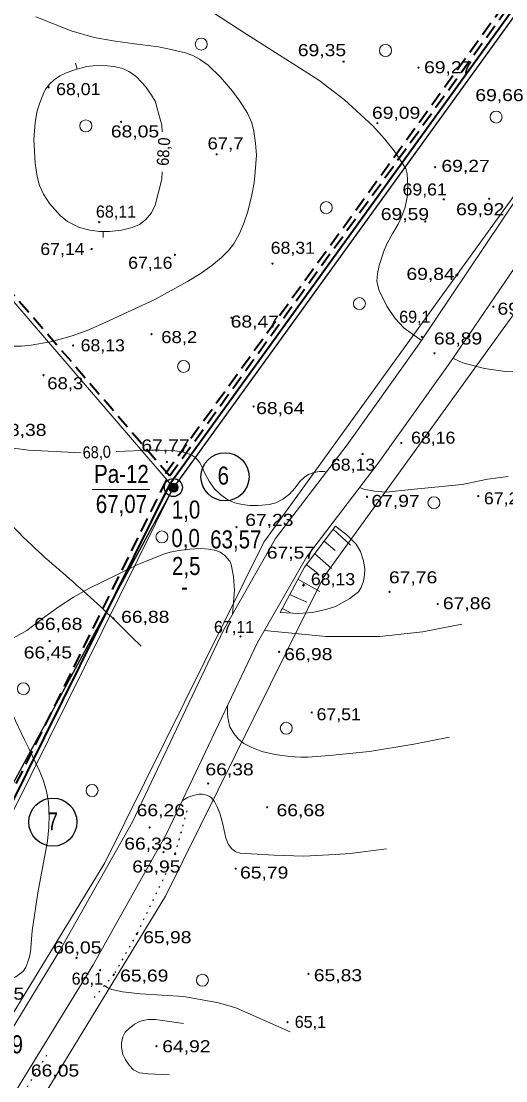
# Model space of a CAD drawing. Extents: x 628176 to 629009, y 6439913 to 6440496.
# Drawn here: x 628522.3 to 628602.9, y 6440112.2 to 6440288.3 of the extents above; entities that cross this region are included whole.
import ezdxf
from ezdxf.enums import TextEntityAlignment as Align

# ---------------------------------------------------------------- set-up
doc = ezdxf.new("R2010")
doc.units = 0
doc.header["$LTSCALE"] = 0.8
doc.linetypes.add('DOTTED', pattern=[1.5, 0.3, -1.2])
doc.linetypes.add('MEDIUM_DASHED', pattern=[4.5, 3, -1.5])
for name, color, linetype, lineweight in [('1', 7, 'Continuous', 13), ('10', 7, 'Continuous', 25), ('11', 7, 'Continuous', 13), ('12', 7, 'Continuous', 13), ('14', 7, 'Continuous', 25), ('16', 7, 'Continuous', 13), ('21', 7, 'MEDIUM_DASHED', 35), ('3', 7, 'Continuous', 13), ('6', 7, 'Continuous', 13)]:
    doc.layers.add(name, color=color, linetype=linetype, lineweight=lineweight)

msp = doc.modelspace()

# ---------------------------------------------------------------- hatches: boundary and pattern name
at = {"layer": '1'}
for points in [[(628576.0425, 6440281.5599, 1), (628575.8425, 6440281.5599, 1)], [(628588.4959, 6440280.5672, 1), (628588.2959, 6440280.5672, 1)], [(628526.9841, 6440277.301, 1), (628526.7841, 6440277.301, 1)], [(628539.0202, 6440271.5559, 1), (628538.8202, 6440271.5559, 1)], [(628581.6671, 6440271.3408, 1), (628581.4671, 6440271.3408, 1)], [(628554.9326, 6440266.1638, 1), (628554.7326, 6440266.1638, 1)], [(628591.2746, 6440264.0147, 1), (628591.0746, 6440264.0147, 1)], [(628592.7042, 6440258.667, 1), (628592.5042, 6440258.667, 1)], [(628600.2509, 6440258.7844, 1), (628600.0509, 6440258.7844, 1)], [(628535.401, 6440254.885, 1), (628535.201, 6440254.885, 1)], [(628589.6342, 6440255.0043, 1), (628589.4342, 6440255.0043, 1)], [(628534.1236, 6440250.4154, 1), (628533.9236, 6440250.4154, 1)], [(628547.9924, 6440249.4589, 1), (628547.7924, 6440249.4589, 1)], [(628564.2251, 6440247.9903, 1), (628564.0251, 6440247.9903, 1)], [(628594.9171, 6440246.1046, 1), (628594.7171, 6440246.1046, 1)], [(628600.9629, 6440240.8324, 1), (628600.7629, 6440240.8324, 1)], [(628557.401, 6440239.0054, 1), (628557.201, 6440239.0054, 1)], [(628544.0917, 6440236.2578, 1), (628543.8917, 6440236.2578, 1)], [(628531.0336, 6440234.3708, 1), (628530.8336, 6440234.3708, 1)], [(628589.0576, 6440235.8239, 1), (628588.8576, 6440235.8239, 1)], [(628591.1757, 6440233.0847, 1), (628590.9757, 6440233.0847, 1)], [(628526.1359, 6440229.434, 1), (628525.9359, 6440229.434, 1)], [(628561.082, 6440224.251, 1), (628560.882, 6440224.251, 1)], [(628585.6579, 6440218.1762, 1), (628585.4579, 6440218.1762, 1)], [(628546.6565, 6440215.0297, 1), (628546.4565, 6440215.0297, 1)], [(628579.2057, 6440216.3368, 1), (628579.0057, 6440216.3368, 1)], [(628579.9466, 6440209.2387, 1), (628579.7466, 6440209.2387, 1)], [(628598.4534, 6440209.3522, 1), (628598.2534, 6440209.3522, 1)], [(628558.2267, 6440204.1828, 1), (628558.0267, 6440204.1828, 1)], [(628567.2897, 6440200.7363, 1), (628567.0897, 6440200.7363, 1)], [(628569.4019, 6440194.5556, 1), (628569.2019, 6440194.5556, 1)], [(628583.6948, 6440193.4364, 1), (628583.4948, 6440193.4364, 1)], [(628591.689, 6440191.4116, 1), (628591.489, 6440191.4116, 1)], [(628537.7623, 6440189.0228, 1), (628537.5623, 6440189.0228, 1)], [(628527.1448, 6440185.2499, 1), (628526.9448, 6440185.2499, 1)], [(628558.8884, 6440186.0188, 1), (628558.6884, 6440186.0188, 1)], [(628565.3116, 6440183.4648, 1), (628565.1116, 6440183.4648, 1)], [(628570.743, 6440173.3816, 1), (628570.543, 6440173.3816, 1)], [(628553.5156, 6440161.5761, 1), (628553.3156, 6440161.5761, 1)], [(628563.3258, 6440157.6225, 1), (628563.1258, 6440157.6225, 1)], [(628543.7771, 6440154.2507, 1), (628543.5771, 6440154.2507, 1)], [(628546.0846, 6440150.1654, 1), (628545.8846, 6440150.1654, 1)], [(628548.0273, 6440149.8668, 1), (628547.8273, 6440149.8668, 1)], [(628558.0998, 6440147.4229, 1), (628557.8998, 6440147.4229, 1)], [(628541.6577, 6440136.6114, 1), (628541.4577, 6440136.6114, 1)], [(628531.6269, 6440132.599, 1), (628531.4269, 6440132.599, 1)], [(628535.5321, 6440130.5527, 1), (628535.3321, 6440130.5527, 1)], [(628537.8175, 6440129.8078, 1), (628537.6175, 6440129.8078, 1)], [(628570.211, 6440129.9301, 1), (628570.011, 6440129.9301, 1)], [(628566.7213, 6440121.9156, 1), (628566.5213, 6440121.9156, 1)], [(628544.8969, 6440117.9094, 1), (628544.6969, 6440117.9094, 1)]]:
    msp.add_hatch(color=256, dxfattribs=at).paths.add_polyline_path(points)
at = {"layer": '10'}
msp.add_hatch(color=256, dxfattribs=at).paths.add_polyline_path([(628548.3757, 6440210.774, 1), (628546.8757, 6440210.774, 1)])

# ---------------------------------------------------------------- linework, layer by layer
at = {"layer": '1'}
for p, q in [((628604.9, 6440259.07), (628588.52, 6440234.65)), ((628611.39, 6440257.62), (628593.63, 6440231.52)), ((628594.82, 6440246.1), (628594.57, 6440246.1)), ((628594.82, 6440246.1), (628594.82, 6440246.35)), ((628594.82, 6440246.1), (628595.07, 6440246.1)), ((628594.82, 6440246.1), (628594.82, 6440245.85)), ((628588.52, 6440234.65), (628576.52, 6440217.86)), ((628593.63, 6440231.52), (628581.69, 6440214.81)), ((628576.52, 6440217.86), (628564.62, 6440202.28)), ((628581.69, 6440214.81), (628569.76, 6440199.19)), ((628577.07, 6440201.21), (628574.21, 6440203.86)), ((628564.62, 6440202.28), (628555.97, 6440187.04)), ((628574.53, 6440200.33), (628572.7, 6440201.87)), ((628569.76, 6440199.19), (628561.61, 6440185)), ((628573.94, 6440197.3), (628571.12, 6440199.79)), ((628571.59, 6440196.52), (628569.72, 6440197.95)), ((628571.98, 6440193.49), (628568.33, 6440195.52)), ((628569.3, 6440194.56), (628569.05, 6440194.56)), ((628569.3, 6440194.56), (628569.3, 6440194.81)), ((628569.3, 6440194.56), (628569.55, 6440194.56)), ((628569.3, 6440194.56), (628569.3, 6440194.31)), ((628569.83, 6440191.73), (628566.97, 6440192.98)), ((628567.04, 6440190), (628565.75, 6440190.69)), ((628555.97, 6440187.04), (628540.83, 6440155.18)), ((628561.61, 6440185), (628546.5, 6440153.23)), ((628540.83, 6440155.18), (628528.77, 6440133.79)), ((628546.5, 6440153.23), (628534.28, 6440131.41)), ((628528.77, 6440133.79), (628516.03, 6440113)), ((628534.28, 6440131.41), (628521.55, 6440110.66))]:
    msp.add_line(p, q, dxfattribs=at)
at = {"layer": '1', "linetype": 'DOTTED', "lineweight": 25}
for p, q in [((628547.93, 6440149.87), (628550.01, 6440157.38)), ((628547.93, 6440149.87), (628541.56, 6440136.61)), ((628541.56, 6440136.61), (628537.72, 6440129.81)), ((628537.72, 6440129.81), (628534.28, 6440125.82)), ((628519.58, 6440105.02), (628527.09, 6440117.27))]:
    msp.add_line(p, q, dxfattribs=at)
at = {"layer": '1'}
msp.add_lwpolyline([(628574.61, 6440204.37), (628569.42, 6440197.55), (628565.37, 6440189.98)], dxfattribs=at)
for centre, radius in [((628552.266, 6440284.4786), 1), ((628582.9206, 6440283.4124), 1), ((628575.9425, 6440281.5599), 0.1), ((628588.3959, 6440280.5672), 0.1), ((628526.8841, 6440277.301), 0.1), ((628601.3148, 6440272.3564), 1), ((628533.0735, 6440270.8839), 1), ((628538.9202, 6440271.5559), 0.1), ((628581.5671, 6440271.3408), 0.1), ((628554.8326, 6440266.1638), 0.1), ((628591.1746, 6440264.0147), 0.1), ((628573.0578, 6440257.2893), 1), ((628592.6042, 6440258.667), 0.1), ((628600.1509, 6440258.7844), 0.1), ((628535.301, 6440254.885), 0.1), ((628589.5342, 6440255.0043), 0.1), ((628534.0236, 6440250.4154), 0.1), ((628547.8924, 6440249.4589), 0.1), ((628564.1251, 6440247.9903), 0.1), ((628594.8171, 6440246.1046), 0.1), ((628578.5646, 6440241.3333), 1), ((628600.8629, 6440240.8324), 0.1), ((628557.301, 6440239.0054), 0.1), ((628543.9917, 6440236.2578), 0.1), ((628530.9336, 6440234.3708), 0.1), ((628588.9576, 6440235.8239), 0.1), ((628591.0757, 6440233.0847), 0.1), ((628549.3338, 6440230.8996), 1), ((628526.0359, 6440229.434), 0.1), ((628560.982, 6440224.251), 0.1), ((628585.5579, 6440218.1762), 0.1), ((628546.5565, 6440215.0297), 0.1), ((628579.1057, 6440216.3368), 0.1), ((628579.8466, 6440209.2387), 0.1), ((628590.9738, 6440208.242), 1), ((628598.3534, 6440209.3522), 0.1), ((628545.7318, 6440202.5545), 1), ((628558.1267, 6440204.1828), 0.1), ((628567.1897, 6440200.7363), 0.1), ((628569.3019, 6440194.5556), 0.1), ((628583.5948, 6440193.4364), 0.1), ((628591.589, 6440191.4116), 0.1), ((628537.6623, 6440189.0228), 0.1), ((628527.0448, 6440185.2499), 0.1), ((628558.7884, 6440186.0188), 0.1), ((628565.2116, 6440183.4648), 0.1), ((628522.6776, 6440177.3207), 1), ((628570.643, 6440173.3816), 0.1), ((628566.4139, 6440170.7558), 1), ((628534.0982, 6440160.4148), 1), ((628553.4156, 6440161.5761), 0.1), ((628563.2258, 6440157.6225), 0.1), ((628543.6771, 6440154.2507), 0.1), ((628545.9846, 6440150.1654), 0.1), ((628547.9273, 6440149.8668), 0.1), ((628557.9998, 6440147.4229), 0.1), ((628541.5577, 6440136.6114), 0.1), ((628531.5269, 6440132.599), 0.1), ((628535.4321, 6440130.5527), 0.1), ((628537.7175, 6440129.8078), 0.1), ((628552.4535, 6440128.8747), 1), ((628570.111, 6440129.9301), 0.1), ((628566.6213, 6440121.9156), 0.1), ((628544.7969, 6440117.9094), 0.1)]:
    msp.add_circle(centre, radius, dxfattribs=at)
at = {"layer": '10'}
for centre, radius in [((628556.2232, 6440212.5587), 4), ((628547.6257, 6440210.774), 0.75), ((628527.5786, 6440155.1573), 4)]:
    msp.add_circle(centre, radius, dxfattribs=at)
at = {"layer": '11'}
for points in [[(628595.11, 6440426.87), (628573.75, 6440350.05), (628485.59, 6440282.78), (628547.63, 6440210.77)], [(628709.76, 6440416.52), (628665.41, 6440371.4), (628640.59, 6440339.47), (628612.95, 6440301.12), (628547.63, 6440210.77)], [(628547.63, 6440210.77), (628520.9, 6440156.84), (628497.5, 6440118.54)]]:
    msp.add_lwpolyline(points, dxfattribs=at)
at = {"layer": '12'}
msp.add_line((628534.13, 6440210.47), (628543.7, 6440210.47), dxfattribs=at)
at = {"layer": '12', "lineweight": 25}
msp.add_circle((628547.6257, 6440210.774), 1.5, dxfattribs=at)
at = {"layer": '14'}
msp.add_lwpolyline([(628648.46, 6440349.59), (628617.39, 6440307.28), (628547.63, 6440210.77), (628497.5, 6440118.54), (628474.19, 6440080.39)], dxfattribs=at)
at = {"layer": '16'}
for points in [[(628523.86, 6440425.63), (628523.12, 6440415.76), (628522.56, 6440410.73), (628519.12, 6440396.74), (628513.8, 6440381.86), (628510.45, 6440374.81), (628499.31, 6440356.42), (628494.72, 6440347.58), (628488, 6440335.91), (628479.91, 6440315.37), (628477.03, 6440304.26), (628475.97, 6440294.36), (628477.03, 6440283.22), (628480.57, 6440271.2), (628486.05, 6440256.7), (628486.58, 6440255.49)], [(628489.38, 6440249.57), (628495.6, 6440238.31), (628503.56, 6440226.46), (628524.07, 6440201.18), (628533.26, 6440193.04), (628542.28, 6440184.38)]]:
    msp.add_spline(points, degree=3, dxfattribs=at)
at = {"layer": '21'}
for points in [[(628595.48, 6440425.23), (628574.45, 6440349.57), (628486.75, 6440282.66), (628547.03, 6440212.69)], [(628704.5, 6440414.58), (628663.6, 6440372.99), (628638.67, 6440340.91), (628611, 6440302.53), (628546.02, 6440212.64)], [(628706.25, 6440415.23), (628664.2, 6440372.46), (628639.31, 6440340.43), (628611.65, 6440302.06), (628547.03, 6440212.69)], [(628546.49, 6440212.09), (628519.5, 6440157.62), (628496.99, 6440120.78)]]:
    msp.add_lwpolyline(points, dxfattribs=at)
at = {"layer": '21', "linetype": 'Continuous', "lineweight": 40}
for points in [[(628708.01, 6440415.87), (628664.8, 6440371.93), (628639.95, 6440339.95), (628612.3, 6440301.59), (628546.94, 6440211.19)], [(628546.94, 6440211.19), (628520.2, 6440157.23), (628496.82, 6440118.96)]]:
    msp.add_lwpolyline(points, dxfattribs=at)
at = {"layer": '3'}
for p, q in [((628524.75, 6440289), (628530.62, 6440286.71)), ((628531.37, 6440281.3), (628531.64, 6440280.33)), ((628545.78, 6440269.88), (628545.69, 6440271)), ((628545.69, 6440262), (628545.77, 6440263.27)), ((628559.29, 6440254.56), (628558.63, 6440253)), ((628585, 6440254.55), (628584.13, 6440253.05)), ((628535.97, 6440252.34), (628535.97, 6440253.34)), ((628584.13, 6440253.05), (628583.23, 6440251.43)), ((628583.32, 6440251.63), (628582.71, 6440250.25)), ((628581.48, 6440244.99), (628581.86, 6440243.53)), ((628581.86, 6440243.53), (628583.13, 6440240.89)), ((628583.13, 6440240.89), (628584.55, 6440238.87)), ((628584.55, 6440238.87), (628586.01, 6440237.27)), ((628586.01, 6440237.27), (628588.89, 6440235.21)), ((628538.09, 6440216.78), (628543.92, 6440217)), ((628543.92, 6440217), (628545.39, 6440217)), ((628583, 6440210), (628587.19, 6440210.42)), ((628544.2, 6440199), (628546, 6440199.68)), ((628554.74, 6440200.28), (628553.48, 6440200.51)), ((628535.63, 6440195), (628541.6, 6440197.9)), ((628541.6, 6440197.9), (628544.2, 6440199)), ((628579.42, 6440196.27), (628579.23, 6440195.18)), ((628579.46, 6440197.18), (628579.42, 6440196.27)), ((628533.55, 6440194), (628535.63, 6440195)), ((628579.23, 6440195.18), (628578.88, 6440194.14)), ((628568.47, 6440189.83), (628565.37, 6440189.98)), ((628557.04, 6440171.01), (628556.74, 6440172.21)), ((628570.02, 6440165.97), (628568.83, 6440165.94)), ((628573.59, 6440166.25), (628570.02, 6440165.97)), ((628526.01, 6440162), (628525.36, 6440163.66)), ((628526.54, 6440160.3), (628526.01, 6440162)), ((628526.54, 6440160.3), (628526.86, 6440158.49)), ((628526.86, 6440158.49), (628526.99, 6440156.33)), ((628526.99, 6440156.33), (628526.9, 6440154.32)), ((628526.9, 6440154.32), (628526.69, 6440151.97)), ((628549.33, 6440121.69), (628544.65, 6440122.35)), ((628539.23, 6440119.46), (628539.61, 6440120.22)), ((628539.61, 6440120.22), (628540.25, 6440120.87)), ((628540.25, 6440120.87), (628541.19, 6440121.59)), ((628539.23, 6440119.46), (628539, 6440118.46)), ((628539, 6440117.69), (628539, 6440118.46)), ((628539, 6440117.69), (628539.23, 6440116.54)), ((628539.61, 6440115.78), (628539.23, 6440116.54)), ((628539.61, 6440115.78), (628540.25, 6440114.75)), ((628543.46, 6440113.29), (628541.99, 6440113.5)), ((628543.46, 6440113.29), (628547.01, 6440113.13))]:
    msp.add_line(p, q, dxfattribs=at)
for points in [[(628552.58, 6440290.77), (628559.18, 6440286.53), (628571.81, 6440278.47), (628576.1, 6440275.19)], [(628530.62, 6440286.71), (628534.44, 6440285.6), (628537.6, 6440285), (628541.55, 6440284.44), (628543.44, 6440284.24), (628545.18, 6440284), (628546.49, 6440283.76), (628549.64, 6440283), (628551, 6440282.53), (628552, 6440282), (628553.39, 6440281), (628555.48, 6440279), (628557.44, 6440276.67), (628558.68, 6440275), (628559.95, 6440273), (628560.68, 6440271.4), (628561.04, 6440270), (628561.31, 6440268), (628561.43, 6440266), (628561.26, 6440263.26), (628561.08, 6440261.44), (628560.7, 6440259.4), (628560, 6440256.67), (628559.29, 6440254.56)], [(628528.79, 6440256), (628527, 6440258), (628526, 6440259.53), (628525.36, 6440261), (628525, 6440262.48), (628524.66, 6440264.66), (628524.44, 6440268.62), (628524.66, 6440271.46), (628525, 6440273.36), (628525.39, 6440274.74), (628526, 6440276.28), (628526.36, 6440277), (628527, 6440277.81), (628527.79, 6440278.52), (628528.72, 6440279.19), (628529.82, 6440279.71), (628531.24, 6440280.22), (628532.39, 6440280.54), (628533.24, 6440280.74), (628533.72, 6440280.81), (628534.28, 6440280.86), (628535.29, 6440280.91), (628536.67, 6440280.86), (628537.75, 6440280.75), (628538.5, 6440280.61), (628539, 6440280.49), (628539.57, 6440280.26), (628540.21, 6440279.94), (628541, 6440279.45), (628541.56, 6440279)], [(628545.69, 6440271), (628544.58, 6440275), (628544, 6440276), (628543, 6440277.45), (628541.56, 6440279)], [(628576.1, 6440275.19), (628580.8, 6440270.89), (628582.75, 6440268.72)], [(628582.75, 6440268.72), (628584.33, 6440266.75), (628586.3, 6440263.8)], [(628586.3, 6440263.8), (628586.54, 6440262.91), (628586.62, 6440260.87), (628586.5, 6440259.06), (628586.16, 6440257.35), (628585.65, 6440255.87), (628585, 6440254.55)], [(628528.79, 6440256), (628530, 6440255), (628532, 6440254), (628533.71, 6440253.55), (628535.32, 6440253.34), (628537, 6440253.34), (628539, 6440253.55), (628540.75, 6440254), (628542, 6440254.51), (628543, 6440255.28), (628544, 6440256.43), (628544.58, 6440257.72), (628545.69, 6440262)], [(628558.63, 6440253), (628557.68, 6440251.29), (628556.82, 6440250.15)], [(628582.71, 6440250.25), (628581.87, 6440247.68), (628581.57, 6440246.37), (628581.48, 6440244.99)], [(628556.82, 6440250.15), (628555.66, 6440249), (628554, 6440247.65), (628552.08, 6440246.3), (628550, 6440245), (628544.53, 6440242), (628537, 6440238.51), (628533.54, 6440237), (628530.82, 6440236), (628529, 6440235.47), (628527.11, 6440235), (628524, 6440234.44), (628522.35, 6440234.29), (628520.65, 6440234.26), (628518.68, 6440234.36)], [(628594.13, 6440232.25), (628595.78, 6440231.52), (628599.36, 6440230.53), (628602.88, 6440230.04), (628605.07, 6440230.1), (628607.25, 6440230.24)], [(628515.25, 6440218.07), (628523.48, 6440217), (628532.28, 6440216.56)], [(628545.39, 6440217), (628547.45, 6440216.92), (628548.69, 6440216.78), (628549.73, 6440216.56), (628550.68, 6440216.16), (628551.37, 6440215.68), (628552.02, 6440214.87), (628552.44, 6440214.17), (628552.94, 6440213.07), (628553.58, 6440211.81), (628554.4, 6440210.62), (628555.54, 6440209.55), (628556.71, 6440208.75), (628557.88, 6440208.25), (628559.05, 6440207.94), (628560.36, 6440207.78), (628561.76, 6440207.78), (628563.57, 6440207.94), (628564.68, 6440208.25), (628565.85, 6440208.83), (628566.95, 6440209.65), (628567.86, 6440210.69), (628568.73, 6440211.81), (628569.48, 6440212.56), (628570.09, 6440212.96), (628571, 6440213.29), (628571.92, 6440213.43), (628572.76, 6440213.43), (628573.07, 6440213.34)], [(628587.19, 6440210.42), (628595.65, 6440211.27), (628599.9, 6440212.15), (628603.33, 6440212.62)], [(628578.61, 6440210.78), (628579.32, 6440210.51), (628581.06, 6440210.15), (628583, 6440210)], [(628579.46, 6440197.18), (628579.27, 6440198.57), (628578.77, 6440200.13), (628578.06, 6440201.33), (628576.61, 6440202.81), (628574.61, 6440204.37)], [(628546, 6440199.68), (628547.1, 6440200), (628548.54, 6440200.32), (628550.38, 6440200.55), (628552.19, 6440200.63), (628553.48, 6440200.51)], [(628554.74, 6440200.28), (628555.43, 6440200), (628556.2, 6440199.5), (628557, 6440198.55), (628557.23, 6440198), (628557.64, 6440196), (628557.77, 6440193.64), (628557.48, 6440189.7)], [(628520.63, 6440185.61), (628521.48, 6440186), (628523.24, 6440187), (628525.88, 6440189), (628528.65, 6440191), (628531, 6440192.55), (628533.55, 6440194)], [(628578.88, 6440194.14), (628578.4, 6440193.44), (628577, 6440192.34), (628574.59, 6440191), (628573, 6440190.47), (628570.75, 6440190), (628568.47, 6440189.83)], [(628562.76, 6440187), (628573, 6440186), (628582, 6440186), (628589.09, 6440186.79), (628595.61, 6440188.07)], [(628522.85, 6440168.85), (628521.36, 6440172), (628518.39, 6440178.54)], [(628556.65, 6440174.57), (628556.65, 6440173.11), (628556.74, 6440172.21)], [(628557.04, 6440171.01), (628557.66, 6440169.87), (628558.44, 6440168.94), (628559.37, 6440168.22), (628560.66, 6440167.54), (628562.37, 6440166.92), (628564.54, 6440166.41), (628566.97, 6440166.04), (628568.83, 6440165.94)], [(628573.59, 6440166.25), (628580.26, 6440166.92), (628587.65, 6440168.11), (628593.55, 6440169.25)], [(628525.36, 6440163.66), (628523.61, 6440167.38), (628522.85, 6440168.85)], [(628558.76, 6440149.99), (628558.03, 6440150.22), (628557.38, 6440150.71), (628556.79, 6440151.46), (628556.36, 6440152.49), (628555.87, 6440154.81), (628555.33, 6440156.63), (628554.86, 6440157.83), (628554.46, 6440158.56), (628553.96, 6440159.18), (628553.59, 6440159.48), (628553.14, 6440159.66), (628552.46, 6440159.78), (628551.91, 6440159.78), (628551.16, 6440159.66), (628550.11, 6440159.31), (628549.12, 6440158.75)], [(628526.69, 6440151.97), (628525.11, 6440143.39), (628524.12, 6440137.09), (628523.84, 6440133.6)], [(628569.35, 6440149.52), (628564.38, 6440149.66), (628558.76, 6440149.99)], [(628569.35, 6440149.52), (628574.52, 6440149.76), (628577.05, 6440149.94), (628583.09, 6440150.7)], [(628523.84, 6440133.6), (628523.68, 6440132.77), (628523.42, 6440131.91), (628523.08, 6440131.06), (628522.69, 6440130.46), (628522.27, 6440130.04), (628521.42, 6440129.44), (628520.68, 6440129.09), (628519.46, 6440128.65), (628518.27, 6440128.4), (628516.94, 6440128.17), (628515.9, 6440127.97), (628515.03, 6440127.75), (628514.61, 6440127.61)], [(628549.35, 6440126.17), (628542.14, 6440126.64), (628539.16, 6440126.97), (628537.37, 6440127.31), (628536.73, 6440127.6), (628536.17, 6440128.02)], [(628567.04, 6440120.3), (628558, 6440124.31), (628555.13, 6440125.14), (628549.35, 6440126.17)], [(628541.19, 6440121.59), (628542, 6440122), (628542.58, 6440122.19)], [(628542.58, 6440122.19), (628543.44, 6440122.35), (628544.65, 6440122.35)], [(628541.99, 6440113.5), (628541, 6440114), (628540.25, 6440114.75)]]:
    msp.add_lwpolyline(points, dxfattribs=at)
at = {"layer": '6'}
for points in [[(628713.84, 6440420.66), (628737.18, 6440419.44), (628678.6, 6440359.86), (628654.6, 6440328.98), (628627.14, 6440290.88), (628627.14, 6440290.88), (628627.14, 6440290.88), (628562.66, 6440201.7), (628536.24, 6440148.38), (628489.22, 6440071.42), (628480.02, 6440052.78), (628457.03, 6440037.16), (628421.17, 6440028.67)], [(628753.89, 6440420.62), (628687.68, 6440352.8), (628636.46, 6440284.16), (628572.54, 6440195.74), (628546.32, 6440142.82), (628546.32, 6440142.82), (628546.32, 6440142.82), (628498.7, 6440064.9), (628484.24, 6440046.28), (628473.72, 6440036.18), (628464.05, 6440028.67)]]:
    msp.add_lwpolyline(points, dxfattribs=at)

# ---------------------------------------------------------------- texts
at = {"layer": '1'}
for s, width, p in [('69,35', 1.2, (628568.33, 6440282.48)), ('69,27', 1.2, (628589.33, 6440279.63)), ('68,01', 1.1, (628528.13, 6440276)), ('69,66', 1.2, (628597.86, 6440275)), ('69,09', 1.2, (628580.67, 6440272.06)), ('68,05', 1.2, (628537.23, 6440268.97)), ('67,7', 1.15, (628553.31, 6440266.98)), ('69,27', 1.2, (628592.22, 6440263.24)), ('69,61', 1.1, (628585.75, 6440259.32)), ('69,92', 1.2, (628594.66, 6440256.03)), ('69,59', 1.2, (628582.13, 6440255.23)), ('67,14', 1.1, (628525.5, 6440249.42)), ('68,31', 1.1, (628563.82, 6440249.62)), ('67,16', 1.1, (628540.11, 6440247.13)), ('69,84', 1.2, (628586.4, 6440245.28)), ('69,68', 1.2, (628601.54, 6440239.5)), ('68,47', 1.2, (628557.16, 6440237.36)), ('68,2', 1.15, (628545.61, 6440234.78)), ('68,89', 1.2, (628590.97, 6440234.55)), ('68,13', 1.1, (628532.2, 6440233.41)), ('68,3', 1.15, (628526.65, 6440227.11)), ('68,64', 1.2, (628561.4, 6440222.98)), ('68,38', 1.2, (628518.49, 6440219.35)), ('67,77', 1.2, (628542.3, 6440216.76)), ('68,16', 1.1, (628587.17, 6440218.06)), ('68,13', 1.1, (628573.84, 6440213.57)), ('67,21', 1.1, (628599.29, 6440207.98)), ('67,97', 1.2, (628580.57, 6440207.55)), ('67,23', 1.2, (628559.58, 6440204.39)), ('67,57', 1.2, (628563.17, 6440198.95)), ('68,13', 1.1, (628570.5, 6440194.54)), ('67,76', 1.2, (628583.49, 6440194.85)), ('67,86', 1.2, (628592.46, 6440190.54)), ('66,68', 1.2, (628524.47, 6440187.1)), ('66,88', 1.2, (628538.94, 6440188.28)), ('66,45', 1.2, (628522.74, 6440182.36)), ('66,98', 1.2, (628566.06, 6440182.08)), ('67,51', 1.1, (628571.45, 6440172.09)), ('66,38', 1.2, (628552.96, 6440162.93)), ('66,26', 1.2, (628541.52, 6440156.14)), ('66,68', 1.2, (628564.79, 6440156.14)), ('66,33', 1.2, (628539.46, 6440150.58)), ('65,95', 1.2, (628540.78, 6440146.78)), ('65,79', 1.2, (628558.72, 6440145.77)), ('65,98', 1.2, (628542.61, 6440135.03)), ('66,05', 1.2, (628527.63, 6440133.32)), ('65,69', 1.2, (628538.77, 6440128.65)), ('65,83', 1.2, (628570.99, 6440128.71)), ('66,05', 1.2, (628514.78, 6440125.64)), ('64,92', 1.2, (628545.78, 6440116.9)), ('66,05', 1.2, (628523.93, 6440112.87))]:
    msp.add_text(s, height=2, dxfattribs=dict(at, width=width)).set_placement(p)
for s, p in [('68,11', (628534.75, 6440255.64)), ('69,1', (628585.2, 6440238.16)), ('67,11', (628554.38, 6440186.59)), ('66,1', (628530.71, 6440128.14)), ('65,1', (628567.82, 6440120.95))]:
    msp.add_text(s, height=2, dxfattribs=at).set_placement(p)
at = {"layer": '10'}
for s, width, p in [('6', 0.85, (628555.93, 6440211.26)), ('7', 0.8, (628527.565, 6440153.8))]:
    msp.add_text(s, height=3, dxfattribs=dict(at, width=width)).set_placement(p, align=Align.CENTER)
at = {"layer": '11', "width": 0.85}
msp.add_text('1,0', height=3, dxfattribs=at).set_placement((628549.735, 6440205.61), align=Align.CENTER)
at = {"layer": '12', "width": 0.85}
for s, p in [('Pa-12', (628538.99, 6440211.54)), ('67,07', (628538.985, 6440206.54)), ('0,0', (628549.665, 6440200.88)), ('63,57', (628558.015, 6440200.65)), ('2,5', (628549.77, 6440196.23)), ('-', (628549.465, 6440192.8)), ('61,49', (628518.34, 6440116.72))]:
    msp.add_text(s, height=3, dxfattribs=at).set_placement(p, align=Align.CENTER)
at = {"layer": '3', "width": 0.9}
for rotation, p in [(86.476, (628546.83, 6440264.21)), (2.179, (628532.58, 6440215.57))]:
    msp.add_text('68,0', height=2, rotation=rotation, dxfattribs=at).set_placement(p)

doc.saveas('drawing.dxf')
